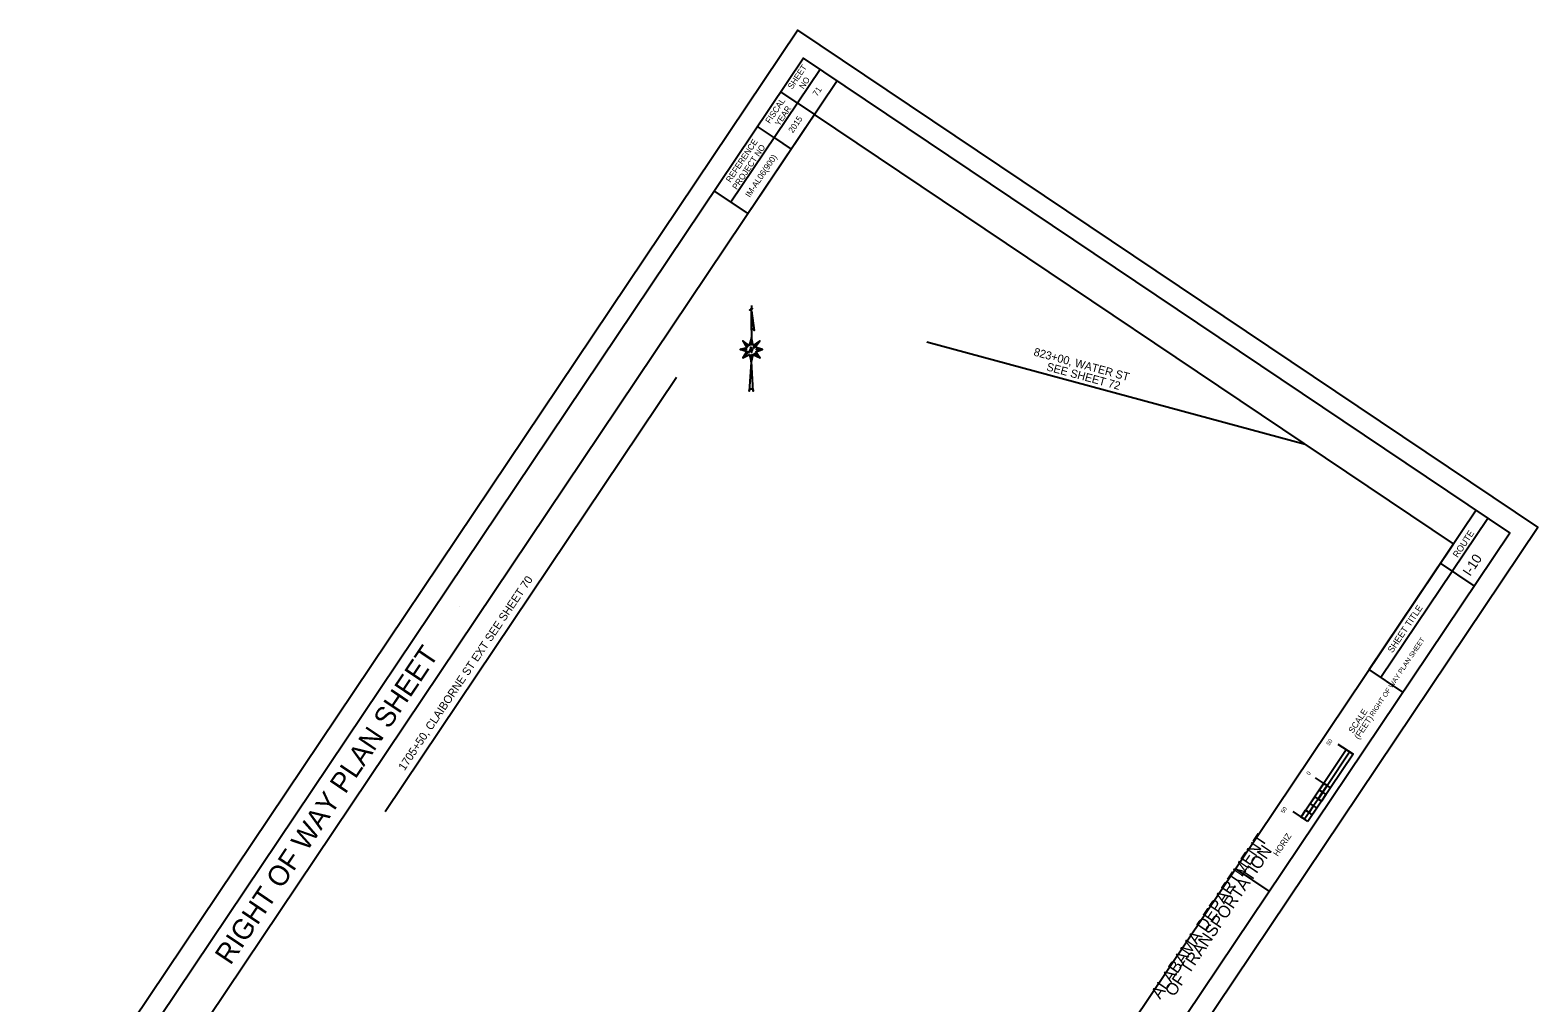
# Model space of a CAD drawing. Extents: x 1797784 to 1799645, y 248583 to 250607.
# Drawn here: x 1797784 to 1799645, y 249407 to 250607 of the extents above; entities that cross this region are included whole.
import ezdxf

# ---------------------------------------------------------------- set-up
doc = ezdxf.new("R2010")
doc.units = 0
for name, color, linetype in [('29', 7, 'Continuous'), ('ANNO-SHT', 7, 'Continuous'), ('ANNO-SYMB', 7, 'Continuous'), ('ANNO-TXT', 7, 'Continuous'), ('DRAINAGE', 7, 'Continuous'), ('Level 1', 7, 'Continuous'), ('Level 57', 7, 'Continuous'), ('Level 6', 7, 'Continuous'), ('Level 62', 7, 'Continuous'), ('SHT-BDR', 7, 'Continuous'), ('SHT-BNDRY', 7, 'Continuous')]:
    doc.layers.add(name, color=color, linetype=linetype)

# ---------------------------------------------------------------- blocks, each defined once
blk = doc.blocks.new('SC47208')
at = {"layer": 'Level 1'}
blk.add_line((0, 0), (0, 0), dxfattribs=at)

msp = doc.modelspace()

# ---------------------------------------------------------------- linework, layer by layer
at = {"layer": '29'}
msp.add_line((1798222.5, 249643.4), (1798582.1, 250179), dxfattribs=at)
msp.add_lwpolyline([(1798891.2, 250222.5), (1799358.1, 250096.4)], dxfattribs=at)
at = {"layer": 'ANNO-SYMB'}
for p, q in [((1799408.9, 249719.5), (1799353.1, 249636.4)), ((1799417.2, 249713.9), (1799361.4, 249630.9)), ((1799417.2, 249713.9), (1799398.9, 249726.1)), ((1799417.2, 249713.9), (1799413, 249716.7)), ((1799417.2, 249713.9), (1799413, 249716.7)), ((1799417.2, 249713.9), (1799413, 249716.7)), ((1799389.3, 249672.4), (1799371, 249684.6)), ((1799389.3, 249672.4), (1799371, 249684.6)), ((1799389.3, 249672.4), (1799371, 249684.6)), ((1799385.2, 249675.2), (1799374, 249658.6)), ((1799385.2, 249675.2), (1799381, 249677.9)), ((1799385.2, 249675.2), (1799381, 249677.9)), ((1799385.2, 249675.2), (1799381, 249677.9)), ((1799361.4, 249630.9), (1799343.2, 249643.1)), ((1799362.9, 249641.9), (1799358.7, 249644.7)), ((1799362.9, 249641.9), (1799358.7, 249644.7))]:
    msp.add_line(p, q, dxfattribs=at)
for points in [[(1799385.2, 249675.2), (1799413, 249716.7), (1799417.2, 249713.9), (1799389.3, 249672.4)], [(1799375.4, 249669.6), (1799381, 249677.9), (1799385.2, 249675.2), (1799379.6, 249666.9)], [(1799364.3, 249653), (1799369.9, 249661.3), (1799374, 249658.6), (1799368.4, 249650.3)], [(1799374, 249658.6), (1799379.6, 249666.9), (1799383.7, 249664.1), (1799378.2, 249655.8)], [(1799353.1, 249636.4), (1799358.7, 249644.7), (1799362.9, 249641.9), (1799357.3, 249633.6)], [(1799362.9, 249641.9), (1799368.4, 249650.3), (1799372.6, 249647.5), (1799367, 249639.2)]]:
    msp.add_lwpolyline(points, close=True, dxfattribs=at)
at = {"layer": 'ANNO-TXT'}
for p, q in [((1799539.4, 249939.7), (1799583.5, 250005.3)), ((1799451.6, 249808.8), (1799539.4, 249939.7))]:
    msp.add_line(p, q, dxfattribs=at)
at = {"layer": 'Level 57'}
msp.add_line((1798674.7, 250267.3), (1798674.6, 250264.8), dxfattribs=at)
for points in [[(1798675.8, 250263.7), (1798675.7, 250263.7), (1798675.8, 250263.5), (1798675.9, 250263.7), (1798675.8, 250263.9), (1798675.6, 250263.8), (1798675.3, 250263.7), (1798675.2, 250263.6), (1798675, 250263.2), (1798674.9, 250262.8), (1798674.7, 250262.2), (1798674.6, 250262.1), (1798674.5, 250261.7), (1798674.5, 250262.3), (1798674.4, 250263.2), (1798674.2, 250263.8), (1798674.3, 250263.2), (1798674.5, 250261.7), (1798674.4, 250263.2), (1798674.2, 250263.8), (1798674.1, 250263.3), (1798673.7, 250262.2), (1798673.4, 250261.7), (1798673.2, 250261.6), (1798672.9, 250261.6), (1798672.8, 250261.7), (1798672.8, 250261.9), (1798672.9, 250262), (1798673, 250261.9), (1798673, 250261.8)], [(1798674.6, 250260.8), (1798678.2, 250236.6), (1798678.1, 250237.4), (1798677.9, 250237.7), (1798677.5, 250238), (1798677, 250238.3), (1798676.7, 250238.3), (1798676.3, 250238.3), (1798675.9, 250238.4), (1798675.6, 250238.2), (1798675.3, 250238.1), (1798674.9, 250237.8), (1798674.8, 250237.6), (1798674.6, 250237.3), (1798674.6, 250237.1), (1798674.6, 250260.6), (1798674.7, 250227.7)], [(1798674.6, 250227.7), (1798674.5, 250218.8), (1798674.6, 250227.8), (1798671.9, 250218.2), (1798664.1, 250223.7), (1798670.2, 250217), (1798664.1, 250223.7), (1798669, 250215.2), (1798661, 250213.2), (1798668.6, 250213), (1798661.1, 250213.4), (1798668.9, 250210.6), (1798664.3, 250202.7), (1798670, 250208.5), (1798664.3, 250202.7), (1798672.2, 250207.1), (1798674.5, 250198.2), (1798674.4, 250206.5), (1798674.5, 250198), (1798676.5, 250207), (1798685.4, 250202.8), (1798676.4, 250207), (1798674.5, 250197.7), (1798672.1, 250161.7), (1798672.3, 250162.9), (1798672.7, 250163.7), (1798673.1, 250164.2), (1798673.8, 250164.6), (1798674.3, 250164.7), (1798674.9, 250164.7), (1798675.4, 250164.5), (1798676, 250164.2), (1798676.4, 250163.7), (1798676.7, 250163.1), (1798676.9, 250162.6), (1798677, 250161.7), (1798674.6, 250198.2), (1798676.4, 250207.1), (1798685.3, 250202.8), (1798678.5, 250208.1), (1798685.2, 250203), (1798680, 250210.1), (1798688, 250213.1), (1798680.4, 250213), (1798688.2, 250213.1), (1798679.4, 250215.9), (1798684.9, 250223.7), (1798678.5, 250217.4), (1798684.9, 250223.7), (1798677, 250218.2), (1798674.7, 250227.6)], [(1798678.5, 250215.7), (1798678.3, 250215.5), (1798678.6, 250215.2), (1798678.7, 250215.6), (1798678.6, 250215.9), (1798678.5, 250216.1), (1798677.9, 250216), (1798677.3, 250215.7), (1798676.3, 250214.5), (1798676.1, 250214), (1798675.8, 250212.8), (1798675.3, 250211.6), (1798674.8, 250210.7), (1798674.7, 250209.3), (1798674.7, 250211.1), (1798674.5, 250213.3), (1798674.4, 250214.5), (1798673.9, 250215.9), (1798673.9, 250214.2), (1798674.1, 250212), (1798674.4, 250210.5), (1798674.7, 250209.4), (1798674.6, 250211.4), (1798674.4, 250214.5), (1798673.9, 250216), (1798673.6, 250214.5), (1798672.9, 250212.9), (1798672.6, 250212.2), (1798672.4, 250211.4), (1798672, 250210.6), (1798671.7, 250210.1), (1798671.4, 250209.5), (1798670.6, 250209.2), (1798670, 250209.3), (1798669.7, 250209.6), (1798669.7, 250210.3), (1798670.1, 250210.6), (1798670.4, 250210.2), (1798670.1, 250210)]]:
    msp.add_lwpolyline(points, dxfattribs=at)
at = {"layer": 'Level 6'}
for p, q in [((1798759.4, 250558.6), (1798649.4, 250394.8)), ((1798780.4, 250544.6), (1798673.8, 250385.8)), ((1798731.2, 250517.3), (1798711, 250530.9)), ((1798731.2, 250517.3), (1798752.5, 250503)), ((1798703.1, 250474.2), (1798682.3, 250488.2)), ((1798703.1, 250474.2), (1798723.8, 250460.3)), ((1798628.9, 250408.6), (1798670.4, 250380.8)), ((1799569.1, 250015), (1799437.2, 249818.5))]:
    msp.add_line(p, q, dxfattribs=at)
at = {"layer": 'Level 62'}
msp.add_lwpolyline([(1798697.7, 248582.5), (1799645.3, 249993.9), (1798732.1, 250607.1), (1797784.5, 249195.7)], close=True, dxfattribs=at)
at = {"layer": 'SHT-BDR'}
msp.add_lwpolyline([(1798705.1, 248728.1), (1799541.2, 249973.5), (1798752.5, 250503), (1797916.4, 249257.7)], close=True, dxfattribs=at)
at = {"layer": 'SHT-BNDRY'}
for p, q in [((1799566.6, 249921.5), (1799525, 249949.4)), ((1799478.7, 249790.6), (1799437.2, 249818.5)), ((1799313.7, 249544.9), (1799272.2, 249572.8))]:
    msp.add_line(p, q, dxfattribs=at)
msp.add_lwpolyline([(1798711.8, 248648.4), (1799610.7, 249987.1), (1798738.9, 250572.4), (1797840.1, 249233.7)], close=True, dxfattribs=at)

# ---------------------------------------------------------------- block references
at = {"layer": 'DRAINAGE', "xscale": 1.000002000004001, "yscale": 1.0000020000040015, "rotation": -60.294516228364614}
msp.add_blockref('SC47208', (1798313.8, 249896.2), dxfattribs=at)
msp.add_blockref('SC47208', (1798313.8, 249896.2), dxfattribs=at)

# ---------------------------------------------------------------- texts
at = {"layer": 'ANNO-SHT'}
for s, height, rotation, p in [('71', 7.45, 56.1222, (1798755.8, 250524.8)), ('2015', 7.45, 56.1222, (1798725.8, 250479.5)), ('IM-AL06(900)', 7.449, 56.1222, (1798672.7, 250400.1)), ('823+00, WATER ST', 10, 344.8847, (1799022.3, 250205.9)), ('SEE SHEET 72', 10, 344.8847, (1799038.1, 250187.6)), ('  I-10  ', 12, 56.1222, (1799556.7, 249925.2)), ('1705+50, CLAIBORNE ST EXT SEE SHEET 70', 10, 56.1222, (1798246.5, 249692.9)), ('               RIGHT OF WAY PLAN SHEET               ', 24.998, 56.1222, (1797954, 249337)), ('               RIGHT OF WAY PLAN SHEET               ', 6, 56.1222, (1799422.9, 249731.5))]:
    msp.add_text(s, height=height, rotation=rotation, dxfattribs=at).set_placement(p)
at = {"layer": 'ANNO-SYMB'}
for s, height, p in [('SCALE', 7.5, (1799417.2, 249739.3)), ('(FEET)', 7.5, (1799424.3, 249731.6)), (' 50', 5, (1799386.9, 249722.6)), ('0', 5, (1799363.4, 249687.5)), ('0', 5, (1799363.4, 249687.5)), ('0', 5, (1799363.4, 249687.5)), (' 50', 5, (1799330.7, 249638.9)), ('HORIZ', 7.5, (1799324.3, 249587.3))]:
    msp.add_text(s, height=height, rotation=56.1794, dxfattribs=at).set_placement(p)
at = {"layer": 'ANNO-TXT'}
for s, height, rotation, p in [('ROUTE', 8, 56.1222, (1799546.4, 249955.7)), ('SHEET TITLE', 8, 56.1222, (1799465.9, 249838.3)), ('ALABAMA DEPARTMENT', 15, 56.1221, (1799179.1, 249410.8)), ('OF TRANSPORTATION', 15, 56.1221, (1799196.2, 249413.9))]:
    msp.add_text(s, height=height, rotation=rotation, dxfattribs=at).set_placement(p)
at = {"layer": 'Level 6'}
for s, p in [('SHEET', (1798725.1, 250533.7)), ('NO', (1798739.1, 250533.8)), ('FISCAL', (1798697.4, 250491.2)), ('YEAR', (1798709.2, 250488.1)), ('REFERENCE', (1798648.7, 250418.6)), ('PROJECT NO', (1798656.6, 250409.7))]:
    msp.add_text(s, height=7.44, rotation=56.1222, dxfattribs=at).set_placement(p)

doc.saveas('drawing.dxf')
